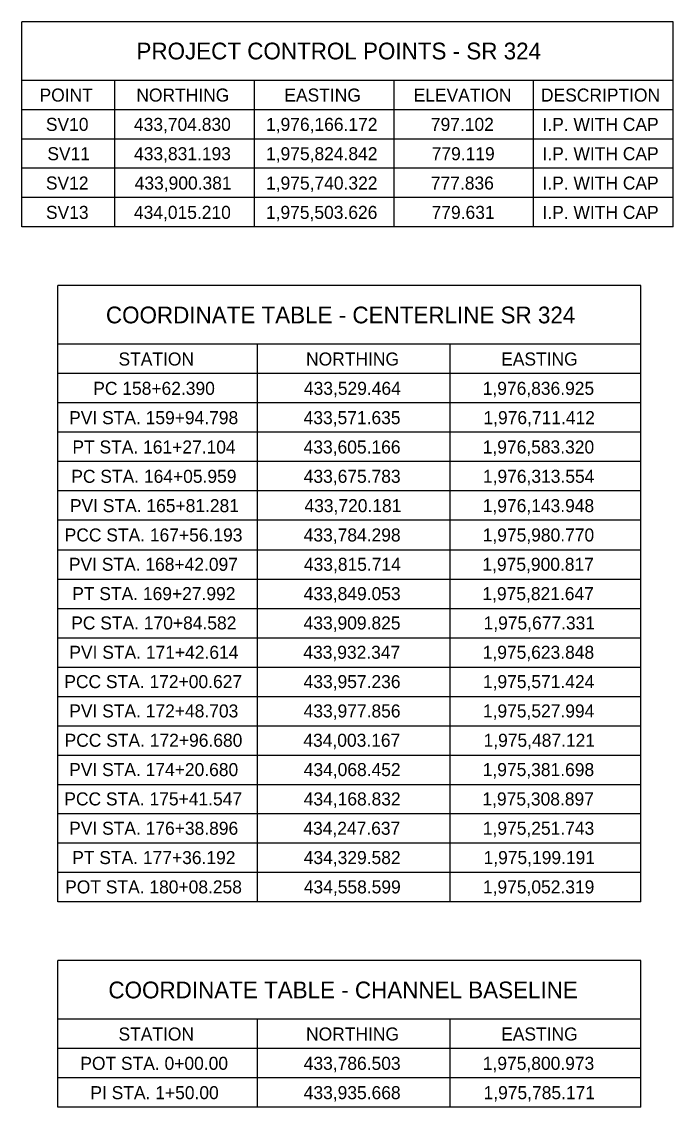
# Model space of a CAD drawing. Extents: x -189 to 370, y -316 to 69.
# Drawn here: x 23.01 to 30.01, y 39.39 to 51.05 of the extents above; entities that cross this region are included whole.
import ezdxf

# ---------------------------------------------------------------- set-up
doc = ezdxf.new("R2010")
doc.units = 0
for name, color, linetype in [('Default', 7, 'Continuous'), ('SH_Text', 7, 'Continuous'), ('ST_Text', 7, 'Continuous')]:
    doc.layers.add(name, color=color, linetype=linetype)

msp = doc.modelspace()

# ---------------------------------------------------------------- linework, layer by layer
at = {"layer": 'SH_Text'}
for p, q in [((23.011, 48.845), (23.011, 51.05)), ((30.011, 51.05), (23.011, 51.05)), ((30.011, 48.845), (30.011, 51.05)), ((30.011, 50.42), (23.011, 50.42)), ((24.011, 48.845), (24.011, 50.42)), ((25.511, 48.845), (25.511, 50.42)), ((27.011, 48.845), (27.011, 50.42)), ((28.511, 48.845), (28.511, 50.42)), ((30.011, 50.105), (23.011, 50.105)), ((30.011, 49.79), (23.011, 49.79)), ((30.011, 49.475), (23.011, 49.475)), ((30.011, 49.16), (23.011, 49.16)), ((30.011, 48.845), (23.011, 48.845)), ((23.399, 41.595), (23.399, 48.215)), ((29.663, 48.215), (23.399, 48.215)), ((29.663, 41.595), (29.663, 48.215)), ((29.663, 47.585), (23.399, 47.585)), ((25.543, 41.595), (25.543, 47.585)), ((27.615, 41.595), (27.615, 47.585)), ((29.663, 47.27), (23.399, 47.27)), ((29.663, 46.955), (23.399, 46.955)), ((29.663, 46.64), (23.399, 46.64)), ((29.663, 46.325), (23.399, 46.325)), ((29.663, 46.01), (23.399, 46.01)), ((29.663, 45.695), (23.399, 45.695)), ((29.663, 45.375), (23.399, 45.375)), ((29.663, 45.06), (23.399, 45.06)), ((29.663, 44.745), (23.399, 44.745)), ((29.663, 44.43), (23.399, 44.43)), ((29.663, 44.115), (23.399, 44.115)), ((29.663, 43.8), (23.399, 43.8)), ((29.663, 43.485), (23.399, 43.485)), ((29.663, 43.17), (23.399, 43.17)), ((29.663, 42.855), (23.399, 42.855)), ((29.663, 42.54), (23.399, 42.54)), ((29.663, 42.225), (23.399, 42.225)), ((29.663, 41.91), (23.399, 41.91)), ((29.663, 41.595), (23.399, 41.595)), ((23.399, 39.39), (23.399, 40.965)), ((29.663, 40.965), (23.399, 40.965)), ((29.663, 39.39), (29.663, 40.965)), ((29.663, 40.335), (23.399, 40.335)), ((25.543, 39.39), (25.543, 40.335)), ((27.615, 39.39), (27.615, 40.335)), ((29.663, 40.02), (23.399, 40.02)), ((29.663, 39.705), (23.399, 39.705)), ((29.663, 39.39), (23.399, 39.39))]:
    msp.add_line(p, q, dxfattribs=at)

# ---------------------------------------------------------------- texts
at = {"layer": 'Default'}
for s, p in [('POINT', (23.203, 50.192)), ('NORTHING', (24.243, 50.192)), ('EASTING', (25.833, 50.192)), ('ELEVATION', (27.222, 50.192)), ('DESCRIPTION', (28.59, 50.192)), ('SV10', (23.271, 49.877)), ('433,704.830', (24.217, 49.877)), ('1,976,166.172', (25.636, 49.877)), ('797.102', (27.407, 49.877)), ('I.P. WITH CAP', (28.606, 49.877)), ('SV11', (23.287, 49.562)), ('433,831.193', (24.218, 49.562)), ('1,975,824.842', (25.636, 49.562)), ('779.119', (27.416, 49.562)), ('I.P. WITH CAP', (28.606, 49.562)), ('SV12', (23.271, 49.247)), ('433,900.381', (24.225, 49.247)), ('1,975,740.322', (25.636, 49.247)), ('777.836', (27.407, 49.247)), ('I.P. WITH CAP', (28.606, 49.247)), ('SV13', (23.272, 48.932)), ('434,015.210', (24.217, 48.932)), ('1,975,503.626', (25.635, 48.932)), ('779.631', (27.415, 48.932)), ('I.P. WITH CAP', (28.606, 48.932)), ('STATION', (24.051, 47.357)), ('NORTHING', (26.066, 47.357)), ('EASTING', (28.162, 47.357)), ('PC 158+62.390', (23.78, 47.042)), ('433,529.464', (26.043, 47.042)), ('1,976,836.925', (27.964, 47.042)), ('PVI STA. 159+94.798', (23.521, 46.727)), ('433,571.635', (26.04, 46.727)), ('1,976,711.412', (27.972, 46.727)), ('PT STA. 161+27.104', (23.556, 46.412)), ('433,605.166', (26.04, 46.412)), ('1,976,583.320', (27.964, 46.412)), ('PC STA. 164+05.959', (23.544, 46.097)), ('433,675.783', (26.041, 46.097)), ('1,976,313.554', (27.966, 46.097)), ('PVI STA. 165+81.281', (23.529, 45.782)), ('433,720.181', (26.049, 45.782)), ('1,976,143.948', (27.964, 45.782)), ('PCC STA. 167+56.193', (23.473, 45.467)), ('433,784.298', (26.041, 45.467)), ('1,975,980.770', (27.964, 45.467)), ('PVI STA. 168+42.097', (23.518, 45.152)), ('433,815.714', (26.043, 45.152)), ('1,975,900.817', (27.961, 45.152)), ('PT STA. 169+27.992', (23.554, 44.837)), ('433,849.053', (26.041, 44.837)), ('1,975,821.647', (27.961, 44.837)), ('PC STA. 170+84.582', (23.543, 44.522)), ('433,909.825', (26.04, 44.522)), ('1,975,677.331', (27.973, 44.522)), ('PVI STA. 171+42.614', (23.523, 44.207)), ('433,932.347', (26.037, 44.207)), ('1,975,623.848', (27.964, 44.207)), ('PCC STA. 172+00.627', (23.469, 43.892)), ('433,957.236', (26.04, 43.892)), ('1,975,571.424', (27.966, 43.892)), ('PVI STA. 172+48.703', (23.522, 43.577)), ('433,977.856', (26.04, 43.577)), ('1,975,527.994', (27.966, 43.577)), ('PCC STA. 172+96.680', (23.472, 43.262)), ('434,003.167', (26.037, 43.262)), ('1,975,487.121', (27.973, 43.262)), ('PVI STA. 174+20.680', (23.521, 42.947)), ('434,068.452', (26.041, 42.947)), ('1,975,381.698', (27.964, 42.947)), ('PCC STA. 175+41.547', (23.469, 42.632)), ('434,168.832', (26.041, 42.632)), ('1,975,308.897', (27.961, 42.632)), ('PVI STA. 176+38.896', (23.521, 42.317)), ('434,247.637', (26.037, 42.317)), ('1,975,251.743', (27.965, 42.317)), ('PT STA. 177+36.192', (23.554, 42.002)), ('434,329.582', (26.041, 42.002)), ('1,975,199.191', (27.973, 42.002)), ('POT STA. 180+08.258', (23.478, 41.687)), ('434,558.599', (26.042, 41.687)), ('1,975,052.319', (27.966, 41.687)), ('STATION', (24.051, 40.107)), ('NORTHING', (26.066, 40.107)), ('EASTING', (28.162, 40.107)), ('POT STA. 0+00.00', (23.641, 39.792)), ('433,786.503', (26.041, 39.792)), ('1,975,800.973', (27.965, 39.792)), ('PI STA. 1+50.00', (23.749, 39.477)), ('433,935.668', (26.041, 39.477)), ('1,975,785.171', (27.973, 39.477))]:
    msp.add_text(s, height=0.14, dxfattribs=at).set_placement(p)
at = {"layer": 'ST_Text'}
for s, p in [('PROJECT CONTROL POINTS - SR 324', (24.244, 50.645)), ('COORDINATE TABLE - CENTERLINE SR 324', (23.916, 47.81)), (' COORDINATE TABLE - CHANNEL BASELINE', (23.876, 40.56))]:
    msp.add_text(s, height=0.18, dxfattribs=at).set_placement(p)

doc.saveas('drawing.dxf')
